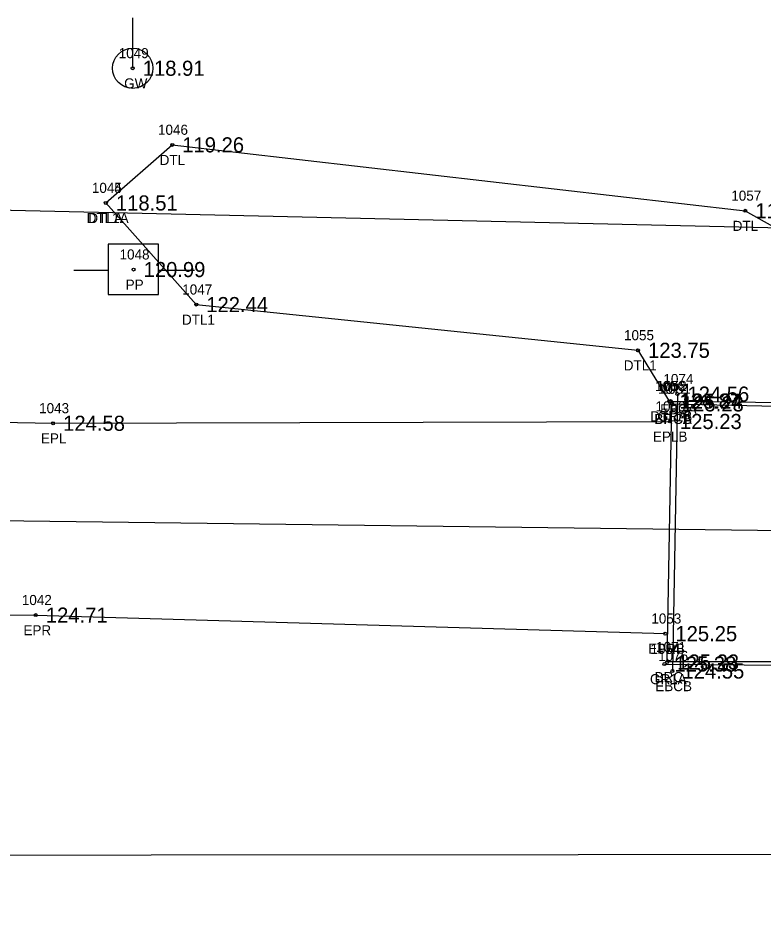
# Model space of a CAD drawing. Extents: x 2374510 to 2377726, y 1024129 to 1025429.
# Drawn here: x 2376407.1 to 2376481.1, y 1024889.6 to 1024978.5 of the extents above; entities that cross this region are included whole.
import ezdxf

# ---------------------------------------------------------------- set-up
doc = ezdxf.new("R2010")
doc.units = 0
for name, color, linetype in [('RD_EX_Bridge', 7, 'Continuous'), ('RD_EX_Bridge_txCode', 7, 'Continuous'), ('RD_EX_GuardRail', 7, 'Continuous'), ('RD_EX_GuardRail_txCode', 7, 'Continuous'), ('RD_EX_H2O', 7, 'Continuous'), ('RD_EX_H2O_txCode', 7, 'Continuous'), ('RD_EX_Road', 7, 'Continuous'), ('RD_EX_Road_txCode', 7, 'Continuous'), ('RD_EX_TX_Bridge_ELEV', 7, 'Continuous'), ('RD_EX_TX_GuardRail_ELEV', 7, 'Continuous'), ('RD_EX_TX_H2O_ELEV', 7, 'Continuous'), ('RD_EX_TX_Road_ELEV', 7, 'Continuous'), ('RD_EX_TX_UT_ELEV', 7, 'Continuous'), ('RD_EX_UT', 7, 'Continuous'), ('RD_EX_UT_txCode', 7, 'Continuous'), ('RD_EX_VEG', 7, 'Continuous'), ('RD_HC_Cl', 7, 'Continuous'), ('RD_HC_Survey_ELEV', 7, 'Continuous'), ('RD_SMD_Locator', 7, 'Continuous')]:
    doc.layers.add(name, color=color, linetype=linetype)

msp = doc.modelspace()

# ---------------------------------------------------------------- linework, layer by layer
at = {"layer": 'RD_EX_Bridge'}
msp.add_line((2376472.614, 1024941.16), (2376472.123, 1024913.663), dxfattribs=at)
msp.add_lwpolyline([(2376472.069, 1024940.192), (2376501.842, 1024939.546), (2376517.17, 1024939.486), (2376531.963, 1024939.436), (2376546.878, 1024939.242), (2376561.806, 1024938.946), (2376561.532, 1024913.624), (2376531.629, 1024914.039), (2376516.542, 1024914.273), (2376501.402, 1024914.445), (2376486.67, 1024914.565), (2376471.602, 1024914.56), (2376472.069, 1024940.192)], dxfattribs=at)
at = {"layer": 'RD_EX_GuardRail'}
for p, q in [((2376471.943, 1024940.469), (2376562.174, 1024939.312)), ((2376471.329, 1024914.358), (2376561.01, 1024913.453))]:
    msp.add_line(p, q, dxfattribs=at)
at = {"layer": 'RD_EX_H2O'}
for points in [[(2376415.874, 1024960.142), (2376422.461, 1024965.913), (2376479.353, 1024959.368), (2376497.525, 1024949.176)], [(2376415.874, 1024960.142), (2376424.844, 1024950.051), (2376468.702, 1024945.512), (2376471.812, 1024940.458)]]:
    msp.add_lwpolyline(points, dxfattribs=at)
at = {"layer": 'RD_EX_Road'}
for points in [[(2375814.75, 1024926.035), (2375866.747, 1024934.161), (2375917.594, 1024939.495), (2375973.625, 1024942.899), (2376030.483, 1024943.846), (2376125.425, 1024942.841), (2376221.255, 1024941.274), (2376314.975, 1024940.077), (2376410.636, 1024938.265), (2376471.87, 1024938.444)], [(2375818.025, 1024906.464), (2375868.666, 1024914.358), (2375919.37, 1024919.491), (2375974.009, 1024923.011), (2376030.207, 1024923.666), (2376124.545, 1024922.832), (2376221.094, 1024921.253), (2376313.999, 1024920.332), (2376408.921, 1024919.216), (2376471.416, 1024917.378)]]:
    msp.add_lwpolyline(points, dxfattribs=at)
at = {"layer": 'RD_EX_UT'}
for p, q in [((2376418.538, 1024973.519), (2376418.538, 1024978.519)), ((2376421.115, 1024956.038), (2376416.115, 1024956.038)), ((2376416.115, 1024956.038), (2376416.115, 1024951.038)), ((2376421.115, 1024951.038), (2376421.115, 1024956.038)), ((2376412.683, 1024953.475), (2376416.153, 1024953.475)), ((2376421.043, 1024953.475), (2376424.683, 1024953.475)), ((2376416.115, 1024951.038), (2376421.115, 1024951.038))]:
    msp.add_line(p, q, dxfattribs=at)
msp.add_circle((2376418.538, 1024973.519), 1.999, dxfattribs=at)
at = {"layer": 'RD_EX_VEG'}
for points in [[(2375821.279, 1024948.024), (2375920.083, 1024958.542), (2375972.688, 1024962.414), (2376124.69, 1024965.868), (2376562.499, 1024955.851), (2376666.612, 1024955.064), (2377217.564, 1024949.87)], [(2375819.707, 1024889.626), (2375920.06, 1024900.346), (2376123.715, 1024895.169), (2376547.516, 1024895.495), (2377115.529, 1024890.134), (2377218.003, 1024892.459)]]:
    msp.add_lwpolyline(points, dxfattribs=at)
at = {"layer": 'RD_HC_Cl'}
msp.add_line((2376010.947, 1024933.689), (2377093.472, 1024919.751), dxfattribs=at)
at = {"layer": 'RD_SMD_Locator'}
for centre in [(2376418.538, 1024973.519), (2376422.461, 1024965.913), (2376415.874, 1024960.142), (2376415.874, 1024960.142), (2376479.353, 1024959.368), (2376418.624, 1024953.529), (2376424.844, 1024950.051), (2376468.702, 1024945.512), (2376472.614, 1024941.16), (2376471.812, 1024940.458), (2376471.943, 1024940.469), (2376472.069, 1024940.192), (2376472.069, 1024940.192), (2376471.87, 1024938.444), (2376410.636, 1024938.265), (2376408.921, 1024919.216), (2376471.416, 1024917.378), (2376471.329, 1024914.358), (2376471.602, 1024914.56), (2376472.123, 1024913.663)]:
    msp.add_circle(centre, 0.15, dxfattribs=at)

# ---------------------------------------------------------------- texts
at = {"layer": 'RD_EX_Bridge_txCode'}
for s, p in [('1074', (2376471.228, 1024942.16)), ('1072', (2376470.683, 1024941.192)), ('1051', (2376470.967, 1024941.192)), ('EBCA', (2376470.897, 1024939.16)), ('BRCA', (2376470.329, 1024938.192)), ('BRCB', (2376470.345, 1024938.192)), ('1071', (2376470.5, 1024915.56)), ('1076', (2376470.713, 1024914.663)), ('BRC', (2376470.35, 1024912.56)), ('EBCB', (2376470.422, 1024911.663))]:
    msp.add_text(s, height=1, dxfattribs=at).set_placement(p)
at = {"layer": 'RD_EX_GuardRail_txCode'}
for s, p in [('1052', (2376470.557, 1024941.469)), ('GRA', (2376470.675, 1024938.469)), ('1054', (2376469.943, 1024915.358)), ('GR1A', (2376469.896, 1024912.358))]:
    msp.add_text(s, height=1, dxfattribs=at).set_placement(p)
at = {"layer": 'RD_EX_H2O_txCode'}
for s, p in [('1046', (2376421.052, 1024966.913)), ('DTL', (2376421.217, 1024963.913)), ('1044', (2376414.488, 1024961.142)), ('1045', (2376414.488, 1024961.142)), ('1057', (2376477.967, 1024960.368)), ('DTL1A', (2376413.977, 1024958.142)), ('DTLA', (2376414.142, 1024958.142)), ('DTL', (2376478.109, 1024957.368)), ('1047', (2376423.458, 1024951.051)), ('DTL1', (2376423.434, 1024948.051)), ('1055', (2376467.316, 1024946.512)), ('DTL1', (2376467.293, 1024943.512)), ('1056', (2376470.402, 1024941.458)), ('DTL1B', (2376469.93, 1024938.458))]:
    msp.add_text(s, height=1, dxfattribs=at).set_placement(p)
at = {"layer": 'RD_EX_Road_txCode'}
for s, p in [('1043', (2376409.25, 1024939.265)), ('1050', (2376470.445, 1024939.444)), ('EPL', (2376409.431, 1024936.265)), ('EPLB', (2376470.193, 1024936.444)), ('1042', (2376407.536, 1024920.216)), ('1053', (2376470.03, 1024918.378)), ('EPR', (2376407.693, 1024917.216)), ('EPRB', (2376469.715, 1024915.378))]:
    msp.add_text(s, height=1, dxfattribs=at).set_placement(p)
at = {"layer": 'RD_EX_TX_Bridge_ELEV'}
for s, p in [('124.56', (2376473.614, 1024940.41)), ('125.23', (2376473.069, 1024939.442)), ('125.23', (2376473.069, 1024939.442)), ('125.23', (2376472.602, 1024913.81)), ('124.55', (2376473.123, 1024912.913))]:
    msp.add_text(s, height=1.5, dxfattribs=at).set_placement(p)
at = {"layer": 'RD_EX_TX_GuardRail_ELEV'}
for s, p in [('125.24', (2376472.943, 1024939.719)), ('125.38', (2376472.329, 1024913.608))]:
    msp.add_text(s, height=1.5, dxfattribs=at).set_placement(p)
at = {"layer": 'RD_EX_TX_H2O_ELEV'}
for s, p in [('119.26', (2376423.461, 1024965.163)), ('118.51', (2376416.874, 1024959.392)), ('118.51', (2376416.874, 1024959.392)), ('118.91', (2376480.353, 1024958.618)), ('122.44', (2376425.844, 1024949.301)), ('123.75', (2376469.702, 1024944.762)), ('124.87', (2376472.812, 1024939.708))]:
    msp.add_text(s, height=1.5, dxfattribs=at).set_placement(p)
at = {"layer": 'RD_EX_TX_Road_ELEV'}
for s, p in [('124.58', (2376411.636, 1024937.515)), ('125.23', (2376472.87, 1024937.694)), ('124.71', (2376409.921, 1024918.466)), ('125.25', (2376472.416, 1024916.628))]:
    msp.add_text(s, height=1.5, dxfattribs=at).set_placement(p)
at = {"layer": 'RD_EX_TX_UT_ELEV'}
msp.add_text('118.91', height=1.5, dxfattribs=at).set_placement((2376419.538, 1024972.769))
at = {"layer": 'RD_EX_UT_txCode'}
for s, p in [('1049', (2376417.152, 1024974.519)), ('GW', (2376417.695, 1024971.519)), ('1048', (2376417.238, 1024954.529)), ('PP', (2376417.844, 1024951.529))]:
    msp.add_text(s, height=1, dxfattribs=at).set_placement(p)
at = {"layer": 'RD_HC_Survey_ELEV'}
msp.add_text('120.99', height=1.5, dxfattribs=at).set_placement((2376419.624, 1024952.779))

doc.saveas('drawing.dxf')
